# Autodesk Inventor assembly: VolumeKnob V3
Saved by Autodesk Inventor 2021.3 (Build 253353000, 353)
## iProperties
Created: 2022-03
Part Number: VolumeKnob V3
Document SubType Name: Assembly
Designer: Administrator
Title: VolumeKnob V3 v6
Author: Administrator
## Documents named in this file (7)
- c:\worker\convert-fusion-r02\tmp\job-1\2145\output\files\5ff5bded-00d4-4c21-b726-8f2d4b528df6\30797f11-82d8-4b6d-8139-af70f6c8b263.iam
- c:\worker\convert-fusion-r02\tmp\job-1\2145\output\files\5ff5bded-00d4-4c21-b726-8f2d4b528df6\snr_608zz_0 v1.ipt
- c:\worker\convert-fusion-r02\tmp\job-1\2145\output\files\5ff5bded-00d4-4c21-b726-8f2d4b528df6\AS5600 Magntic encoder v1.ipt
- c:\worker\convert-fusion-r02\tmp\job-1\2145\output\files\5ff5bded-00d4-4c21-b726-8f2d4b528df6\Component1.ipt
- c:\worker\convert-fusion-r02\tmp\job-1\2145\output\files\5ff5bded-00d4-4c21-b726-8f2d4b528df6\Component2.ipt
- c:\worker\convert-fusion-r02\tmp\job-1\2145\output\files\5ff5bded-00d4-4c21-b726-8f2d4b528df6\Component3.ipt
- c:\worker\convert-fusion-r02\tmp\job-1\2145\output\files\5ff5bded-00d4-4c21-b726-8f2d4b528df6\Component4.ipt
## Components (6 placed, 6 different names)
1. snr_608zz_0 v1:1
2. AS5600 Magntic encoder v1:1
3. Component1:1
4. Component2:1
5. Component3:1
6. Component4:1
